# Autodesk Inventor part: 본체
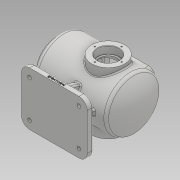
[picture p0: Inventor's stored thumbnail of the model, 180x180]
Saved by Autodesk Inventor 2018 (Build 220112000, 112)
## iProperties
Created: 2021-11
Part Number: 본체
Material: 일반
Document SubType Name: Modeling
Designer: home
Density: 1 g/cm^3
Appearance: 기본값
Author: home
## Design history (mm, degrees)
sketch "스케치1"
  geometry: L1 (-105, 32.5)-(-105, 47.5); L2 (-105, 47.5)-(-95, 47.5); L3 (-95, 47.5)-(-95, 65); L4 (-95, 65)-(80.993, 65); L5 (-105, 0)-(105, 0); L6 (-105, 32.5)-(-80, 32.5); L7 (-80, 32.5)-(-80, 55); L8 (-80, 55)-(76.239, 55); L9 (95, 0)-(105, 0); A1 r 100 centre (5, 0) between (105, 0) and (80.993, 65); A2 r 90 centre (5, 0) between (95, 0) and (76.239, 55); 2 further points
  constraints: 18 end point, 4 perpendicular, 4 point on circle, 3 vertical, 2 centre point, 2 coincident, 2 horizontal, 1 tangent
  dimensions: "d0" = 210 distance of L5.start L5.end; "d1" = 47.5 distance of L5.start L1.end; "d2" = 10 distance of L1.end L2.end; "d3" = 17.5 distance of L2.end L3.end; "d8" = 10 distance of L9.start L5.end; "d9" = 90 distance of L9.start A1.centre; "d11" = 32.5 distance of L1.start L5.start; "d12" = 25 distance of L1.start L6.end; "d13" = 22.5 distance of L6.end L7.end; "d14" = 65 diameter of L6 L5; "d15" = 95 diameter of L2 L5 (derived); "d16" = 110 diameter of L8 L5 (derived); "d17" = 130 diameter of L4 L5 (derived); "d18" = 0 distance from line of point (0, 0) L9; "d19" = 80 distance from line of point (0, 0) L7
revolve "회전1" sketch "스케치1" stored, may be unused: angle "d20" = 90 deg
node "작업 평면1"
sketch "스케치2"
  geometry: L1 (0, 0)-(0, -114); L2 (0, -114)-(-65, -114); L3 (0, -114)-(65, -114); L4 (-65, -114)-(-65, -100); L5 (-65, -100)-(65, -100); L6 (65, -100)-(65, -114)
  constraints: 12 end point, 2 vertical, 1 horizontal, 1 perpendicular, 1 point on line
  dimensions: "d22" = 114 distance of L1.start L1.end; "d23" = 65 distance of L1.end L2.end; "d24" = 65 distance of L1.end L3.end; "d25" = 14 distance of L2.end L4.end; "d26" = 130 distance of L4.end L5.end
extrude "돌출1" join sketch "스케치2" distance "d27" = 160; taper "d28" = 0 deg
node "작업 평면2"
sketch "스케치6"
  geometry: L1 (-105, -47.5)-(-105, 47.5) reference; C1 r 40 at (22, 0); 1 further point
  constraints: 1 centre point
  dimensions: "d61" = 80 diameter of C1; "d62" = 127 distance from line of C1.centre L1; "d63" = 22 distance of C1.centre point (0, 0)
extrude "돌출3" join sketch "스케치6" stored distance "d64" = 160; taper "d65" = 0 deg
sketch "스케치7"
  geometry: C1 r 40 at (0, 0) reference; C2 r 26 at (0, 0); 1 further point
  constraints: 1 centre point, 1 coincident
  dimensions: "d66" = 52 diameter of C2
extrude "돌출4" cut sketch "스케치7" distance "d67" = 18; taper "d68" = 0 deg
sketch "스케치8"
  geometry: C1 r 26 at (0, 0) reference; C2 r 21 at (0, 0); 1 further point
  constraints: 1 centre point, 1 coincident
  dimensions: "d69" = 42 diameter of C2
extrude "돌출5" cut sketch "스케치8" extent not by distance; stored distance "d70" = 18; taper "d71" = 0 deg
node "작업 평면3"
sketch "스케치9"
  geometry: L1 (105, 47.5)-(105, -47.5) reference; L2 (55, 0)-(55, -30); L3 (55, -30)-(-65, -30); L4 (-65, -30)-(-65, 30); L5 (-65, 30)-(55, 30); L6 (55, 30)-(55, 0); 1 further point
  constraints: 10 end point, 2 perpendicular, 1 parallel, 1 point on line
  dimensions: "d74" = 30 distance of L2.start L2.end; "d75" = 120 distance of L2.end L3.end; "d76" = 60 distance of L3.end L4.end; "d77" = 120 distance of L4.end L5.end; "d78" = 50 distance between parallel lines of L2 L1; "d79" = 17.5 distance from line of L1.start L5
extrude "돌출6" join sketch "스케치9" stored distance "d80" = 18; taper "d81" = 0 deg
sketch "스케치11"
  geometry: L1 (-55, 30)-(65, 30) reference; L2 (65, -30)-(-55, -30) reference; L3 (-50, 0)-(60, 0); L4 (-64, 156)-(-64, 106); L5 (5, 0)-(5, 25); L6 (5, 0)-(5, -25); 5 further points
  constraints: 8 end point, 4 coincident, 2 vertical, 1 horizontal, 1 midpoint, 1 point on line
  dimensions: "d93" = 110 distance of L3.start L3.end; "d94" = 50 distance of L4.start L4.end; "d96" = 25 distance of L5.start L5.end; "d97" = 25 distance of L5.start L6.end; "d98" = 30 distance between parallel lines of L2 L3; "d99" = 69 distance between parallel lines of L6 L4; "d100" = 60 distance from line of L1.end L6; "d101" = 186 distance from line of L4.start L2
hole "구멍1" sketch "스케치11" at (5, 25), (60, 0), (5, -25), (-50, 0) diameter "d102" = 3.242; stored, may be unused: countersink angle "d106" = 90 deg, drill point angle "d108" = 118 deg; dims "d103" = 9, "d104" = 4, "d105" = 2, "d107" = 11
sketch "스케치12" dims "d109" = 65
  geometry: C1 r 21 at (0, 0) reference; 6 further points
  constraints: 1 coincident, 1 vertical alignment, 2 other
  dimensions: "d113" = 54.5 distance of point (-22, 0) point (32.5, 0); "d114" = 39.24602 distance of point (-22, 0) point (0, 32.5); "d115" = 39.24602 distance of point (-22, 0) point (0, -32.5); "d116" = 10.5 distance of point (-22, 0) point (-32.5, 0); "d117" = 32.5 distance of point (32.5, 0) C1.centre; "d118" = 32.5 distance of point (0, -32.5) C1.centre; "d119" = 32.5 distance of point (-32.5, 0) C1.centre
hole "구멍2" sketch "스케치12" at (0, 32.5), (-32.5, 0), (0, -32.5), (32.5, 0) diameter "d120" = 3.242; stored, may be unused: countersink angle "d124" = 90 deg, drill point angle "d126" = 118 deg; dims "d121" = 11, "d122" = 4, "d123" = 2, "d125" = 13
sketch "스케치13" dims "d127" = 80
  geometry: 6 further points
  constraints: 1 coincident, 1 vertical alignment, 7 other
  dimensions: "d130" = 360 deg dimension on point (0, 0) point (0, 40) (derived)
hole "구멍3" sketch "스케치13" at (0, 40), (-40, 0), (0, -40), (40, 0) diameter "d132" = 3.242; stored, may be unused: countersink angle "d136" = 90 deg, drill point angle "d138" = 118 deg; dims "d133" = 11, "d134" = 4, "d135" = 2, "d137" = 13
fillet "모깎기1" dims "d139" = 20
fillet "모깎기2" dims "d146" = 10
chamfer "모따기1" distance "d147" = 1; stored, may be unused: second distance "d148" = 2, angle "d149" = 45 deg
fillet "모깎기3" dims "d150" = 15
fillet "모깎기4" dims "d152" = 3
sketch "스케치16"
  geometry: L1 (0, 0)-(120, 0) reference; L2 (-20, 11)-(-20, 0) reference; 2 further points
  constraints: 1 other
  dimensions: "d156" = 5 distance from line of L1 point (60, 5); "d157" = 80 distance from line of point (60, 5) L2
feature "엠보싱1" sketch "스케치16" dims "d0" = 210, "d1" = 47.5, "d2" = 10, "d3" = 17.5, "d8" = 10, "d9" = 90, "d11" = 32.5, "d12" = 25, "d13" = 22.5, "d14" = 65, "d15" = 95 (derived), "d16" = 110 (derived), "d17" = 130 (derived), "d18" = 0, "d19" = 80, "d158" = 0.5, "d159" = 0
fillet "모깎기8" dims "d160" = 3
sketch "스케치23"
  geometry: L1 (-72, -100)-(-55, -100) reference; L2 (-55, -100)-(-41.308, -62.383); L3 (-55, -114)-(65, -114) reference; L4 (65, -100)-(51.308, -62.383); L5 (65, -114)-(65, -103) reference; L6 (-55, -100)-(65, -100); L7 (-41.308, -62.383)-(51.308, -62.383); L8 (-85, -65)-(76.239, -65) reference; 2 further points
  constraints: 8 end point, 1 horizontal, 1 parallel
  dimensions: "d216" = 110 deg angle of L1 L2; "d217" = 160 deg angle of L4 L5; "d219" = 22.53194 distance from line of point (76.239, -65) L4; "d221" = 13.69153 distance from line of L4.end L5
extrude "돌출11" join sketch "스케치23" stored distance "d223" = 14; taper "d224" = 0 deg
node "작업 평면4"
sketch "스케치25"
  geometry: L1 (-7, -100)-(7, -100) reference; L2 (-50, -100)-(-33.809, -55.515); L3 (-62, -100)-(-45, -100) reference; 2 further points
  constraints: 2 end point, 2 other
  dimensions: "d237" = 110 deg angle of L3 L2; "d238" = 53.56248 distance from line of L1.end L2; "d239" = 0 distance from line of L2.start L3
feature "리브8" sketch "스케치25" dims "d240" = 1, "d241" = 14, "d242" = 0, "d243" = 0, "d244" = 1, "d245" = 1
sketch "스케치26"
  geometry: L1 (-55, -7)-(-55, 7) reference; L2 (-45, 0)-(-45, 20); L3 (-45, 20)-(55, 20); L4 (55, 20)-(55, -20); L5 (55, -20)-(-45, -20); L6 (-45, -20)-(-45, 0); 1 further point
  constraints: 10 end point, 2 perpendicular, 1 horizontal, 1 vertical
  dimensions: "d249" = 20 distance of L2.start L2.end; "d250" = 100 distance of L2.end L3.end; "d251" = 40 distance of L3.end L4.end; "d252" = 100 distance of L4.end L5.end; "d253" = 110 distance between parallel lines of L1 L4; "d254" = 20 distance from line of point (0, 0) L3
extrude "돌출12" cut sketch "스케치26" distance "d255" = 30; taper "d256" = 0 deg
fillet "모깎기11" dims "d257" = 5
fillet "모깎기12" dims "d258" = 3
sketch "스케치27"
  geometry: C1 r 9 at (0, -17); C2 r 9 at (120, -17); C3 r 9 at (120, -107); C4 r 9 at (0, -107); A1 r 20 centre (0, -17) between (0, 3) and (-20, -17) reference; A2 r 20 centre (120, -17) between (140, -17) and (120, 3) reference; A3 r 20 centre (120, -107) between (120, -127) and (140, -107) reference; A4 r 20 centre (0, -107) between (-20, -107) and (0, -127) reference; 1 further point
  constraints: 4 centre point, 4 coincident
  dimensions: "d259" = 18 diameter of C1; "d260" = 18 diameter of C2; "d261" = 18 diameter of C3; "d262" = 18 diameter of C4
extrude "돌출13" cut sketch "스케치27" distance "d263" = 2; taper "d264" = 0 deg
sketch "스케치28"
  geometry: C1 r 4.5 at (0, 0); C2 r 4.5 at (0, -90); C3 r 4.5 at (120, -90); C4 r 4.5 at (120, 0); A1 r 20 centre (0, 0) between (0, 20) and (-20, 0) reference; A2 r 20 centre (0, -90) between (-20, -90) and (0, -110) reference; A3 r 20 centre (120, -90) between (120, -110) and (140, -90) reference; A4 r 20 centre (120, 0) between (140, 0) and (120, 20) reference; 1 further point
  constraints: 4 centre point, 4 coincident
  dimensions: "d265" = 9 diameter of C1; "d266" = 9 diameter of C2; "d267" = 9 diameter of C3; "d268" = 9 diameter of C4
extrude "돌출14" cut sketch "스케치28" extent not by distance; stored distance "d269" = 2; taper "d270" = 0 deg
fillet "모깎기13" dims "d271" = 3
fillet "모깎기14" dims "d272" = 3
fillet "모깎기15" dims "d273" = 0.3
node "솔리드1"
mirror "미러3"
mirror "미러4"
mirror "미러5"
mirror "미러13"
other parameters: "d59" = 75, "d235" = -73
